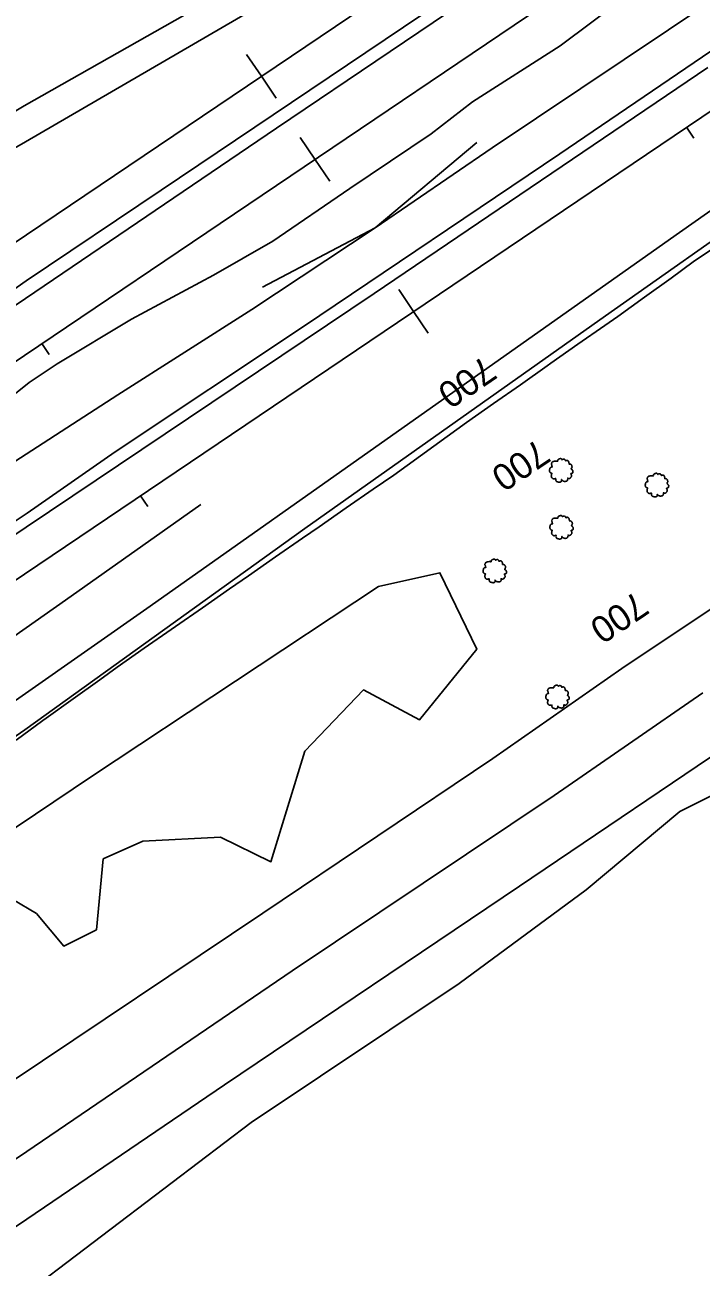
# Model space of a CAD drawing. Extents: x 1901471 to 1963503, y 756461 to 799997.
# Drawn here: x 1913299.4 to 1913504.7, y 762412.7 to 762789.9 of the extents above; entities that cross this region are included whole.
import ezdxf

# ---------------------------------------------------------------- set-up
doc = ezdxf.new("R2010")
doc.units = 0
for name, color, linetype in [('RD_DTM_BkLn1', 7, 'Continuous'), ('RD_EX_Fence_Other', 7, 'Continuous'), ('RD_EX_H2O', 7, 'Continuous'), ('RD_EX_Road', 7, 'Continuous'), ('RD_EX_VEG', 7, 'Continuous'), ('RD_HC_Cl', 7, 'Continuous'), ('RD_HC_Data_Tic', 7, 'Continuous'), ('RD_HC_TX_Sta50', 7, 'Continuous')]:
    doc.layers.add(name, color=color, linetype=linetype)

# ---------------------------------------------------------------- blocks, each defined once
blk = doc.blocks.new('T2')
at = {"layer": 'RD_EX_VEG'}
for points in [[(0.05233333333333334, 7.213166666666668), (-0.24750000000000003, 7.238166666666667), (-0.5723333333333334, 7.138166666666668), (-0.8222500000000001, 7.038250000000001), (-1.0471666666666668, 6.963250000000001), (-1.2720833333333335, 6.863250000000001), (-1.5719166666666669, 6.688416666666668), (-1.7968333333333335, 6.488416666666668), (-1.9218333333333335, 6.2385833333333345), (-1.9718333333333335, 6.013666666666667), (-2.0217500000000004, 5.738833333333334), (-2.0217500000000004, 5.563833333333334), (-2.146666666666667, 5.538833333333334), (-2.296666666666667, 5.563833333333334), (-2.5465000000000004, 5.638833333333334), (-2.796416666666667, 5.638833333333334), (-3.0463333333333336, 5.638833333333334), (-3.3961666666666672, 5.613833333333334), (-3.7460000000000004, 5.613833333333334), (-4.020833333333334, 5.563833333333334), (-4.345750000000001, 5.513916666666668), (-4.720583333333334, 5.389000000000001), (-5.0704166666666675, 5.264000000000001), (-5.37025, 5.014083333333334), (-5.620166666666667, 4.539333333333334), (-5.745166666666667, 4.189500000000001), (-5.895083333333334, 3.9395833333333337), (-5.745166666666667, 3.489833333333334), (-5.570166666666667, 3.139916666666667), (-5.545250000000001, 2.9400000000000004), (-5.470250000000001, 2.5152500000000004), (-5.37025, 2.2903333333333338), (-5.245333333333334, 2.0903333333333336), (-5.320250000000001, 2.065416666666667), (-5.695166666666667, 2.015416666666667), (-5.995000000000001, 1.9155000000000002), (-6.419833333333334, 1.6905833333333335), (-6.644750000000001, 1.465666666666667), (-6.744750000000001, 1.1407500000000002), (-6.769666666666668, 0.7909166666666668), (-6.869583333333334, 0.5910833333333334), (-6.944583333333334, 0.3161666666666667), (-6.969583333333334, 0.2411666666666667), (-7.019583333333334, -0.08366666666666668), (-6.9195833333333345, -0.5335000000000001), (-6.894583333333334, -0.8833333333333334), (-6.769666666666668, -1.1082500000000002), (-6.619750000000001, -1.2830833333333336), (-6.444833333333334, -1.5330000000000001), (-6.045000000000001, -1.7579166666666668), (-5.7201666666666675, -1.8579166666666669), (-5.520250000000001, -1.8828333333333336), (-5.695166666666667, -2.382666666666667), (-5.745166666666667, -2.7325000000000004), (-5.870083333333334, -3.132333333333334), (-5.870083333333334, -3.2072500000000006), (-5.920000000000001, -3.682083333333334), (-5.770166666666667, -4.007000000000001), (-5.695166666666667, -4.38175), (-5.520250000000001, -4.606666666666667), (-5.245333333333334, -4.906583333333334), (-4.9205000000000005, -5.131416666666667), (-4.420666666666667, -5.256416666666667), (-4.020833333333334, -5.231416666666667), (-3.4460833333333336, -5.056500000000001), (-3.1962500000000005, -4.9815000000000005), (-3.2212500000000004, -5.156416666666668), (-3.1962500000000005, -5.531333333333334), (-3.1962500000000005, -5.956083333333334), (-3.0463333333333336, -6.280916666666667), (-2.946333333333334, -6.555833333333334), (-2.796416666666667, -6.805750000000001), (-2.4715000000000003, -7.030583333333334), (-2.07175, -7.1055833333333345), (-1.6469166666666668, -7.2555000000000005), (-1.1970833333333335, -7.330500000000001), (-0.6973333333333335, -7.355500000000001), (-0.09758333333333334, -7.205583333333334), (0.17725000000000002, -7.080583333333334), (0.27725000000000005, -6.905666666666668), (0.47716666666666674, -6.530833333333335), (0.4271666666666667, -6.3059166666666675), (0.4521666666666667, -5.706166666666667), (0.5520833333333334, -5.881166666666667), (0.7270833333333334, -6.231000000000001), (1.2268333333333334, -6.530833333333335), (1.626666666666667, -6.705750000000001), (2.101416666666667, -6.8557500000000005), (2.4013333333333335, -6.930666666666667), (2.8760833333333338, -6.8557500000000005), (3.2510000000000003, -6.780750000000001), (3.6257500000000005, -6.655750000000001), (3.9256666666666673, -6.380916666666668), (4.100583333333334, -6.106000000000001), (4.1505833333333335, -5.831166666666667), (4.2255, -5.456333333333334), (4.275500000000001, -5.281416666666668)], [(4.275500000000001, -5.281416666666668), (4.200583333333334, -5.106416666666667), (4.1505833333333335, -4.856583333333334), (4.2255, -4.881583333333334), (4.4004166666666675, -4.931583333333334), (4.675333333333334, -5.056500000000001), (4.900250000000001, -5.131416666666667), (5.225083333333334, -5.106416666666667), (5.500000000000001, -5.006500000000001), (5.949750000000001, -4.731583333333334), (6.224666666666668, -4.256833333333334), (6.499500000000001, -3.8570000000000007), (6.5745000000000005, -3.5321666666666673), (6.524500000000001, -3.3072500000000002), (6.499500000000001, -2.8075000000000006), (6.299583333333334, -2.5575833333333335), (6.249583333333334, -2.432666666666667), (6.1496666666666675, -2.0328333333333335), (6.224666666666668, -1.9828333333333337), (6.499500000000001, -1.9328333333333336), (6.874333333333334, -1.8079166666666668), (7.149250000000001, -1.6830000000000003), (7.374166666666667, -1.5080000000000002), (7.449083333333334, -1.2830833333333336), (7.424166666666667, -0.8833333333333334), (7.4740833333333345, -0.48350000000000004), (7.399166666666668, -0.3335), (7.299166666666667, -0.1836666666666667), (7.224166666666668, 0.016333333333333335), (7.074250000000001, 0.16616666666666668), (6.974333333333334, 0.3161666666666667), (6.874333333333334, 0.41608333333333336), (6.749416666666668, 0.5660833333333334), (6.5745000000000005, 0.6910000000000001), (6.424583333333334, 0.7410000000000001), (6.374583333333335, 0.8909166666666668), (6.524500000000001, 1.0908333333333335), (6.5745000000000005, 1.1907500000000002), (6.599416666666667, 1.4156666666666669), (6.824416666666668, 1.7655000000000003), (6.874333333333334, 2.1653333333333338), (6.824416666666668, 2.590166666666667), (6.774416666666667, 2.8650833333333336), (6.624416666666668, 3.139916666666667), (6.424583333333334, 3.3898333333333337), (6.299583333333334, 3.5647500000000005), (6.124666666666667, 3.689666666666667), (5.799833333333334, 3.814666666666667), (5.549916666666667, 3.864583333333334), (5.200083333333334, 3.864583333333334), (5.000166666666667, 3.9145833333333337), (5.025166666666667, 3.964583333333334), (5.025166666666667, 4.1145000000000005), (5.025166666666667, 4.389416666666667), (4.950166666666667, 4.839166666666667), (4.800250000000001, 5.339), (4.800250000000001, 5.364000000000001), (4.7002500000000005, 5.613833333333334), (4.475416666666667, 5.813750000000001), (4.3005, 5.913666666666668), (4.100583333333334, 6.038666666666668), (3.850666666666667, 6.063666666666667), (3.5508333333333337, 6.063666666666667), (3.2759166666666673, 6.013666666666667), (3.0760000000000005, 5.913666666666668), (2.9010833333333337, 5.788750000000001), (2.8260833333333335, 5.938666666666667), (2.726166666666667, 6.2385833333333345), (2.676166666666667, 6.3885000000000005), (2.52625, 6.563416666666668), (2.301416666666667, 6.7633333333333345), (1.8515000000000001, 6.888250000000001), (1.2268333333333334, 6.813333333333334), (0.9269166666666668, 6.613416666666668), (0.7770000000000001, 6.438500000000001), (0.7270833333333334, 6.563416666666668), (0.5270833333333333, 6.7633333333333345), (0.4271666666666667, 6.938250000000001), (0.25225000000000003, 7.063250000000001), (0.10233333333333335, 7.163166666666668), (0.0023333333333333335, 7.213166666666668)]]:
    blk.add_spline(points, degree=3, dxfattribs=at)

msp = doc.modelspace()

# ---------------------------------------------------------------- linework, layer by layer
at = {"layer": 'RD_DTM_BkLn1'}
for points in [[(1913459.1287386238, 762687.1713342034), (1913467.3296330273, 762692.892382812), (1913475.530527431, 762698.6134314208), (1913479.3819162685, 762701.3002094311), (1913487.4891290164, 762707.1543311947), (1913495.5963417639, 762713.0084529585), (1913502.3433786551, 762717.8804079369), (1913510.638795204, 762723.4643922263)], [(1913296.8284717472, 762572.6895249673), (1913304.877119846, 762578.6238242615), (1913305.9254736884, 762579.3967795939), (1913314.0613900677, 762585.211020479), (1913322.197306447, 762591.0252613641), (1913327.50803486, 762594.8205135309), (1913335.6896814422, 762600.5703473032), (1913343.8713280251, 762606.3201810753), (1913345.1548272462, 762607.2221886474), (1913353.3771575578, 762612.9136856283), (1913361.5994878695, 762618.6051826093), (1913367.3552433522, 762622.5893165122), (1913375.5587405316, 762628.3058544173), (1913383.7622377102, 762634.0223923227), (1913388.7652241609, 762637.5086812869), (1913396.9887888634, 762643.1975704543), (1913405.2123535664, 762648.8864596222), (1913411.3977339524, 762653.1653757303), (1913419.5105685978, 762659.0118750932), (1913427.6234032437, 762664.8583744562), (1913433.502857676, 762669.0953924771), (1913441.6744705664, 762674.8594713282), (1913449.8460834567, 762680.6235501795), (1913458.0176963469, 762686.3876290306), (1913459.1287386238, 762687.1713342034)]]:
    msp.add_lwpolyline(points, dxfattribs=at)
at = {"layer": 'RD_EX_Fence_Other'}
for points in [[(1912151.7100000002, 761913.2700000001), (1912211.4500000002, 761952.3800000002), (1912318.4600000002, 762023.2800000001), (1912425.7100000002, 762092.9800000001), (1912520.1500000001, 762154.57), (1912587.6000000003, 762198.1800000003), (1912735.2900000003, 762294.1300000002), (1912856.2400000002, 762372.6200000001), (1912963.9300000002, 762442.9800000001), (1913098.8300000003, 762530.32), (1913193.9600000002, 762591.1400000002), (1913287.6900000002, 762651.7300000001), (1913327.7000000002, 762677.4900000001), (1913368.3000000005, 762703.4600000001), (1913405.7700000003, 762728.2100000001), (1913441.3200000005, 762752.5200000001), (1913508.2400000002, 762797.3900000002)], [(1913371.6100000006, 762710.2600000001), (1913405.7700000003, 762728.2100000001), (1913436.6200000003, 762754.1700000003)], [(1912667.5000000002, 761887.4300000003), (1912688.7900000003, 761925.8900000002), (1912721.4800000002, 761980.6200000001), (1912763.5000000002, 762038.58), (1912800.5900000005, 762082.32), (1912831.6300000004, 762117.8900000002), (1912847.2800000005, 762135.6800000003), (1912879.5600000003, 762168.0200000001), (1912904.9700000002, 762190.9600000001), (1913057.2900000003, 762306.1300000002), (1913096.6200000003, 762334.2200000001), (1913156.6200000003, 762374.7600000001), (1913206.9900000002, 762408.3700000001), (1913295.2800000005, 762468.9700000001), (1913371.6300000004, 762520.1800000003), (1913441.4500000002, 762567.1400000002), (1913480.6800000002, 762594.4000000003), (1913520.7900000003, 762621.3)]]:
    msp.add_lwpolyline(points, dxfattribs=at)
at = {"layer": 'RD_EX_H2O'}
msp.add_lwpolyline([(1913640.9200000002, 762904.5400000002), (1913589.7300000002, 762870.6600000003), (1913548.9400000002, 762842.58), (1913514.0000000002, 762819.7700000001), (1913480.7000000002, 762797.6600000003), (1913461.9000000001, 762783.4900000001), (1913435.3400000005, 762766.4600000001), (1913422.7600000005, 762756.8), (1913398.1100000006, 762740.2200000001), (1913374.7300000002, 762724.2100000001), (1913356.6800000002, 762713.9200000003), (1913331.7800000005, 762700.5100000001), (1913309.2900000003, 762686.9100000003), (1913300.7700000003, 762681.32), (1913272.6300000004, 762658.81), (1913211.5100000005, 762616.3800000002), (1913153.6800000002, 762579.6600000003), (1913084.2100000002, 762533.3800000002), (1913035.4000000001, 762499.08), (1912998.0200000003, 762470.83), (1912865.0000000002, 762381.7900000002), (1912798.1700000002, 762339.3500000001), (1912733.9700000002, 762296.81), (1912714.8400000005, 762276.8)], dxfattribs=at)
at = {"layer": 'RD_EX_Road'}
for points in [[(1912043.4900000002, 761860.05), (1912064.9200000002, 761874.5900000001), (1912211.2700000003, 761972.3500000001), (1912324.5700000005, 762049.31), (1912399.7800000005, 762099.6500000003), (1912459.8500000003, 762140.1800000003), (1912548.4000000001, 762199.9400000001), (1912641.9700000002, 762262.4300000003), (1912747.2600000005, 762333.5000000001), (1912880.39, 762424.4500000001), (1912977.9400000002, 762489.8600000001), (1913066.9100000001, 762549.6300000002), (1913157.7500000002, 762610.8600000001), (1913257.6000000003, 762678.58), (1913299.6800000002, 762706.83), (1913375.8600000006, 762758.5400000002), (1913444.8700000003, 762805.1600000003), (1913512.8400000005, 762851.1700000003)], [(1912578.9600000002, 762224.9600000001), (1912626.2700000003, 762257.3), (1912686.5500000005, 762297.9100000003), (1912756.0500000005, 762344.7000000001), (1912799.5900000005, 762374.4200000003), (1912869.9300000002, 762421.83), (1912963.9200000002, 762485.3600000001), (1913040.7400000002, 762536.9600000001), (1913101.0300000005, 762577.7800000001), (1913156.0800000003, 762614.9400000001), (1913204.4300000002, 762647.8), (1913252.5800000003, 762679.9400000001), (1913287.7500000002, 762703.8), (1913299.89, 762712.1700000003), (1913340.8300000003, 762739.6300000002), (1913414.3800000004, 762789.2200000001), (1913499.7700000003, 762846.4600000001)], [(1912051.4900000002, 761800.1700000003), (1912144.9900000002, 761863.0300000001), (1912227.2000000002, 761918.5200000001), (1912339.14, 761993.5300000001), (1912440.4000000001, 762061.8500000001), (1912497.1500000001, 762100.4200000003), (1912620.9500000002, 762183.3400000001), (1912719.5700000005, 762249.9700000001), (1912832.3700000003, 762326.8400000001), (1912958.2000000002, 762411.1600000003), (1913057.7500000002, 762478.2600000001), (1913160.0900000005, 762547.2200000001), (1913253.5900000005, 762610.6000000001), (1913300.1100000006, 762641.6500000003), (1913326.89, 762660.2500000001), (1913384.0500000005, 762698.33), (1913461.7800000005, 762750.7000000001), (1913545.9500000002, 762807.9500000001)], [(1913376.2500000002, 762809.0400000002), (1913299.2600000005, 762765.2400000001), (1913281.6800000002, 762754.8800000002), (1913205.2700000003, 762710.7100000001), (1913139.5400000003, 762671.9800000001), (1913132.2200000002, 762668.5300000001), (1913066.9100000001, 762630.1200000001), (1912957.8400000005, 762568.3600000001), (1912892.5300000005, 762531.9400000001), (1912861.5500000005, 762516.55), (1912815.7100000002, 762494.57), (1912768.4000000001, 762476.3600000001), (1912692.8300000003, 762450.7200000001), (1912644.2700000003, 762436.9000000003), (1912604.9200000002, 762428.5300000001), (1912558.4400000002, 762420.05)], [(1913368.0200000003, 762794.1000000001), (1913299.6800000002, 762754.3500000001), (1913199.6200000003, 762696.7900000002), (1913121.1200000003, 762651.3600000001), (1913047.4400000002, 762608.9700000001), (1912966.2200000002, 762562.7100000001), (1912911.5800000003, 762532.6700000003), (1912876.4200000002, 762515.0900000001), (1912834.9700000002, 762495.83), (1912784.1000000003, 762475.0000000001), (1912738.89, 762458.6700000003), (1912692.0000000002, 762443.81), (1912629.2000000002, 762427.8), (1912559.9100000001, 762414.82), (1912513.0200000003, 762408.1200000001), (1912464.6700000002, 762403.6200000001), (1912410.6600000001, 762401.1100000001), (1912346.8100000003, 762400.4800000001), (1912283.6000000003, 762403.5200000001), (1912222.2600000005, 762410.2200000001), (1912168.0500000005, 762416.9100000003), (1912084.3100000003, 762427.9000000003), (1912029.6800000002, 762435.7500000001), (1912007.9100000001, 762441.2000000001)], [(1913587.6100000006, 762789.6500000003), (1913498.2000000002, 762726.83), (1913412.8100000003, 762666.6100000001), (1913337.5200000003, 762613.3700000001), (1913299.64, 762586.8800000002), (1913247.5400000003, 762550.4800000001), (1913143.1100000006, 762477.56), (1913037.5200000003, 762403.9500000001), (1912980.0700000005, 762362.55), (1912916.5700000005, 762314.5200000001), (1912861.9100000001, 762270.0900000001), (1912825.8600000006, 762236.9500000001), (1912785.39, 762195.7800000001), (1912744.9200000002, 762149.9600000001), (1912704.9400000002, 762100.4300000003), (1912698.3300000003, 762091.2200000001), (1912671.2500000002, 762053.3600000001), (1912648.9000000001, 762018.4900000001), (1912625.4400000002, 761979.2100000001), (1912601.5100000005, 761937.58), (1912575.2200000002, 761889.8), (1912536.1800000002, 761819.2000000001), (1912511.1500000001, 761773.7000000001)], [(1912052.0500000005, 761796.0100000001), (1912052.8000000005, 761796.5200000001), (1912081.3600000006, 761815.7100000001), (1912119.4800000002, 761841.6500000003), (1912176.1000000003, 761879.5900000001), (1912225.5700000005, 761912.9300000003), (1912291.2400000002, 761957.1800000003), (1912333.7000000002, 761985.8), (1912394.9000000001, 762027.1800000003), (1912447.9500000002, 762062.56), (1912503.1600000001, 762100.1800000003), (1912554.4300000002, 762134.3800000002), (1912619.7900000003, 762178.4500000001), (1912682.5900000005, 762220.7800000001), (1912756.5500000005, 762270.6700000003), (1912825.6300000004, 762317.1900000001), (1912919.8300000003, 762381.0400000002), (1913005.1900000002, 762438.3700000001), (1913070.0800000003, 762481.8600000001), (1913138.2300000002, 762528.2600000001), (1913226.14, 762587.81), (1913299.8700000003, 762637.3500000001), (1913405.4900000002, 762708.3500000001), (1913506.7400000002, 762776.9300000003)], [(1913524.5200000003, 762735.8900000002), (1913475.7200000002, 762701.56), (1913384.4000000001, 762636.9900000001), (1913299.4100000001, 762575.83), (1913192.8800000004, 762502.2100000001), (1913051.4700000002, 762404.1800000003), (1912997.7400000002, 762366.1500000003), (1912940.2900000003, 762324.5200000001), (1912881.6800000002, 762279.05), (1912846.3300000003, 762248.1100000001), (1912802.3700000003, 762204.7300000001), (1912747.7100000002, 762143.9100000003), (1912713.7000000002, 762100.1900000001), (1912698.7500000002, 762080.0100000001), (1912668.3600000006, 762037.2800000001), (1912632.9800000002, 761980.3600000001), (1912596.8600000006, 761915.9600000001), (1912554.0100000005, 761839.1000000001), (1912516.14, 761769.9700000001)], [(1913061.2400000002, 762440.9300000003), (1913154.6900000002, 762505.7200000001), (1913220.9700000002, 762551.4300000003), (1913253.5300000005, 762574.2200000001), (1913286.7900000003, 762597.7100000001), (1913311.7600000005, 762615.2200000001), (1913352.8100000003, 762644.2700000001)], [(1912950.2000000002, 762203.3400000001), (1912976.1600000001, 762224.9700000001), (1913000.2000000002, 762242.83), (1913024.0900000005, 762259.9300000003), (1913044.1500000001, 762273.8), (1913066.6700000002, 762289.0400000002), (1913108.0100000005, 762317.6800000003), (1913146.8800000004, 762344.32), (1913197.4200000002, 762378.5900000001), (1913259.3600000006, 762420.1400000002), (1913291.6300000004, 762442.2500000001), (1913300.0100000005, 762447.81), (1913380.5900000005, 762502.6600000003), (1913460.1100000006, 762555.9100000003), (1913505.2800000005, 762587.05)], [(1913519.0800000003, 762575.2800000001), (1913449.6000000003, 762528.31), (1913360.0400000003, 762468.0000000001), (1913300.0100000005, 762427.2100000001), (1913257.1600000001, 762398.5000000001), (1913208.2700000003, 762365.6100000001), (1913147.9800000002, 762324.07), (1913111.7200000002, 762299.7600000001), (1913075.1800000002, 762274.6900000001), (1913044.5600000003, 762253.4000000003), (1913017.7800000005, 762234.9300000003), (1912986.1900000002, 762210.9000000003)]]:
    msp.add_lwpolyline(points, dxfattribs=at)
at = {"layer": 'RD_EX_VEG'}
for points in [[(1913290.8100000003, 762542.3500000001), (1913319.9300000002, 762561.8600000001), (1913406.8100000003, 762619.3600000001), (1913425.4200000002, 762623.5000000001), (1913436.5900000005, 762600.33), (1913419.2200000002, 762578.82), (1913402.2600000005, 762587.9200000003), (1913384.4700000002, 762569.3), (1913374.1200000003, 762535.7900000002), (1913358.8200000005, 762543.2400000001), (1913335.2300000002, 762542.0000000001), (1913323.2400000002, 762536.6200000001), (1913321.1700000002, 762515.1100000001), (1913311.2400000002, 762510.1400000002), (1913302.9700000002, 762520.07), (1913295.7700000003, 762524.2700000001)], [(1913009.7800000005, 762216.3600000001), (1913086.7100000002, 762263.5100000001), (1913166.4700000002, 762312.9600000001), (1913215.7400000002, 762343.0900000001), (1913263.6000000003, 762378.9000000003), (1913280.6200000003, 762392.7200000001), (1913296.2200000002, 762401.9400000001), (1913368.1000000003, 762456.6100000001), (1913431.3100000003, 762498.8500000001), (1913469.8300000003, 762527.2700000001), (1913498.2500000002, 762551.0400000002), (1913522.6900000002, 762563.2600000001)]]:
    msp.add_lwpolyline(points, dxfattribs=at)
at = {"layer": 'RD_HC_Cl'}
for p, q in [((1916236.554148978, 764707.5798489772), (1911792.3681539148, 761708.9425405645)), ((1916252.3823139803, 764682.0580289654), (1911757.6532124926, 761649.3514215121)), ((1916195.7651138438, 764578.0862627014), (1911854.4508108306, 761647.9472216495))]:
    msp.add_line(p, q, dxfattribs=at)
at = {"layer": 'RD_HC_Data_Tic'}
for p, q in [((1913371.228122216, 762774.2508807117), (1913366.7535575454, 762780.8824922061)), ((1913371.228122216, 762774.2508807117), (1913375.702686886, 762767.6192692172)), ((1913500.2788893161, 762758.7871127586), (1913502.51665056, 762755.471630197)), ((1913387.4986246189, 762749.0490537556), (1913383.0240942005, 762755.6806883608)), ((1913387.4986246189, 762749.0490537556), (1913391.9731550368, 762742.4174191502)), ((1913417.3918252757, 762702.8430816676), (1913412.9163027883, 762709.4740467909)), ((1913417.3918252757, 762702.8430816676), (1913421.8673477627, 762696.2121165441)), ((1913304.6031920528, 762693.1174235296), (1913306.8404572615, 762689.8016062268)), ((1913334.5047612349, 762646.8990505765), (1913336.7425224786, 762643.5835680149))]:
    msp.add_line(p, q, dxfattribs=at)

# ---------------------------------------------------------------- block references
at = {"layer": 'RD_EX_VEG', "xscale": 0.4921259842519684, "yscale": 0.4921259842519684}
for p in [(1913462.14, 762654.6300000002), (1913491.2000000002, 762650.1800000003), (1913462.2400000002, 762637.3600000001), (1913441.9700000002, 762624.1200000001), (1913461.0000000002, 762585.8500000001)]:
    msp.add_blockref('T2', p, dxfattribs=at)

# ---------------------------------------------------------------- texts
at = {"layer": 'RD_HC_TX_Sta50'}
for rotation, p in [(214.00882459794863, (1913438.8747132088, 762689.6091681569)), (214.00852866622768, (1913455.144778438, 762664.4069918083)), (214.01710034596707, (1913485.0506411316, 762618.211140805))]:
    msp.add_text('700', height=8.000000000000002, rotation=rotation, dxfattribs=at).set_placement(p)

doc.saveas('drawing.dxf')
